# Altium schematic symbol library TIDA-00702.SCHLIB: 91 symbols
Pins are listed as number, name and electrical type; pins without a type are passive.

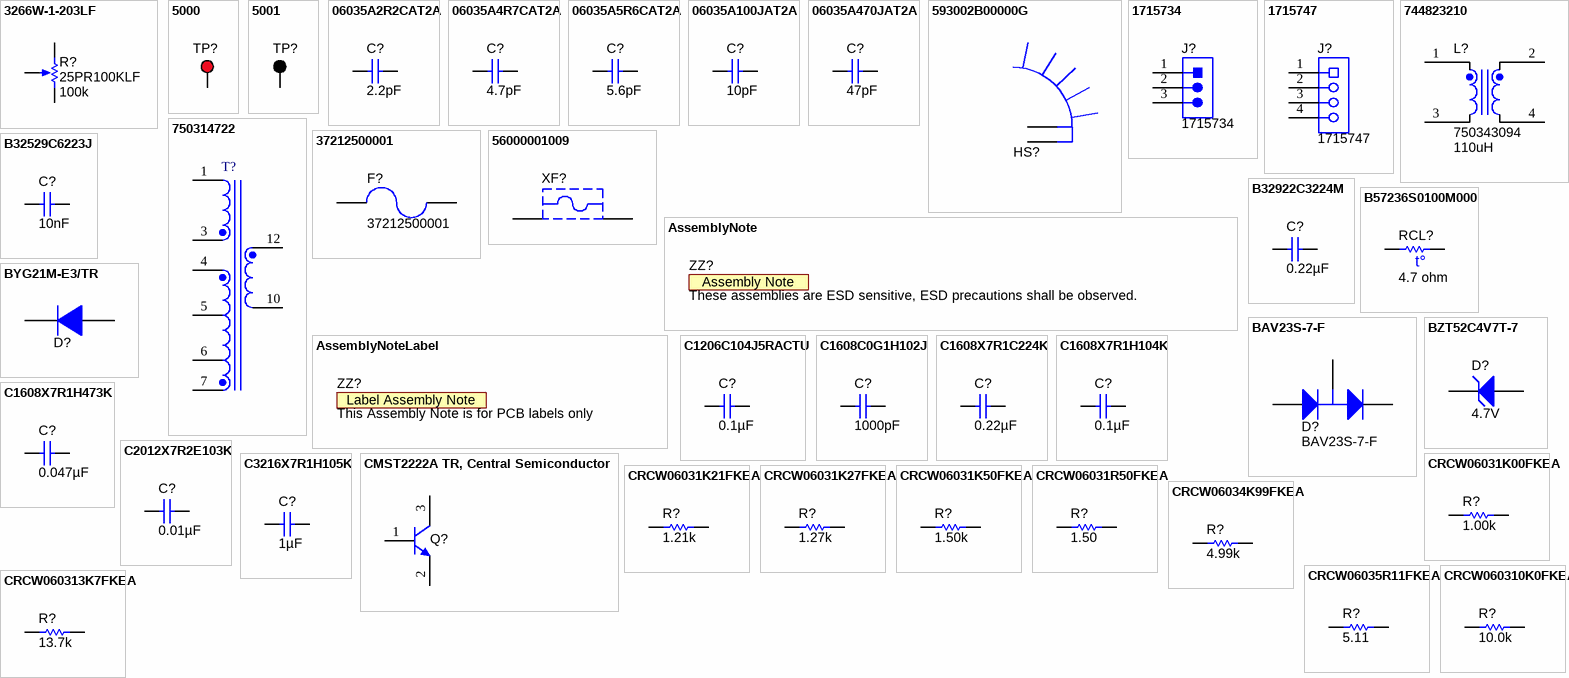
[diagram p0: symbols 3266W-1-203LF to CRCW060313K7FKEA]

## 3266W-1-203LF
designator R?, comment 25PR100KLF  value 100k
TRIMMER 100K OHM 0.5W TH; Manufacturer: TT Electronics/BI; Sim Note: Enter the Resistance value and the set point into parameter fields.
simulation model POT (Potentiometer)
footprint TRIM_3266W
footprint POT_25PXXXXXX (Potentiometer, 25p series, through hole, 3 pin)
pins: 1 CCW, 2 WIPER, 3 CW
1 alternate drawing of the same symbol

## 5000
designator TP?  (value not drawn)
Test Point, Miniature, Red, TH; Manufacturer: Keystone; CompType: Test Point Loop; U/M: EA
footprint Keystone5000
pins: 1

## 5001
designator TP?  (value not drawn)
Test Point, Miniature, Black, TH; Manufacturer: Keystone; CompType: Test Point Loop; U/M: EA
footprint Keystone5001 (For Keystone 500x miniature loop terminals)
pins: 1

## 06035A2R2CAT2A
designator C?  ValueDisplayed: 2.2pF  (hidden comment: 06035A2R2CAT2A)
CAP, CERM, 2.2 pF, 50 V, +/- 11%, C0G/NP0, 0603; Manufacturer: AVX; Polarized: N; CompType: Capacitor; Value: 2.2pF; U/M: EA; Cap_F: 0.0000000000022; Tolerance_%: 11; ESR_ohm: 1.033; Value1: 1.033 ohm; VDC_V: 50; Value2: 50V; TaMin_C: -55; TaMax_C: 125; Cap_Case: 0603
signal-integrity model Cap
simulation model Cap
footprint 0603
footprint 0603M
footprint 0603L
footprint 0603_HV
footprint 0603S
pins: 1, 2

## 06035A4R7CAT2A
designator C?  ValueDisplayed: 4.7pF  (hidden comment: 06035A4R7CAT2A)
CAP, CERM, 4.7 pF, 50 V, +/- 5%, C0G/NP0, 0603; Manufacturer: AVX; Polarized: N; CompType: Capacitor; Value: 4.7pF; U/M: EA; Cap_F: 0.0000000000047; Tolerance_%: 5; ESR_ohm: 0.633; Value1: 0.633 ohm; VDC_V: 50; Value2: 50V; TaMin_C: -55; TaMax_C: 125; Cap_Case: 0603
signal-integrity model Cap
simulation model Cap
footprint 0603
footprint 0603M
footprint 0603L
footprint 0603_HV
footprint 0603S
pins: 1, 2

## 06035A5R6CAT2A
designator C?  ValueDisplayed: 5.6pF  (hidden comment: 06035A5R6CAT2A)
CAP, CERM, 5.6 pF, 50 V, +/- 5%, C0G/NP0, 0603; Manufacturer: AVX; Polarized: N; CompType: Capacitor; Value: 5.6pF; U/M: EA; Cap_F: 0.0000000000056; Tolerance_%: 5; ESR_ohm: 0.568; Value1: 0.568 ohm; VDC_V: 50; Value2: 50V; TaMin_C: -55; TaMax_C: 125; Cap_Case: 0603
signal-integrity model Cap
simulation model Cap
footprint 0603
footprint 0603M
footprint 0603L
footprint 0603_HV
footprint 0603S
pins: 1, 2

## 06035A100JAT2A
designator C?  ValueDisplayed: 10pF  (hidden comment: 06035A100JAT2A)
CAP, CERM, 10 pF, 50 V, +/- 5%, C0G/NP0, 0603; Manufacturer: AVX; Polarized: N; CompType: Capacitor; Value: 10pF; U/M: EA; Cap_F: 0.00000000001; Tolerance_%: 5; ESR_ohm: 0.403; Value1: 0.403 ohm; VDC_V: 50; Value2: 50V; TaMin_C: -55; TaMax_C: 125; Cap_Case: 0603
signal-integrity model Cap
simulation model Cap
footprint 0603
footprint 0603M
footprint 0603L
footprint 0603_HV
footprint 0603S
pins: 1, 2

## 06035A470JAT2A
designator C?  ValueDisplayed: 47pF  (hidden comment: 06035A470JAT2A)
CAP, CERM, 47 pF, 50 V, +/- 5%, C0G/NP0, 0603; Manufacturer: AVX; Polarized: N; CompType: Capacitor; Value: 47pF; U/M: EA; Cap_F: 0.000000000047; Tolerance_%: 5; ESR_ohm: 0.174; Value1: 0.174 ohm; VDC_V: 50; Value2: 50V; TaMin_C: -55; TaMax_C: 125; Cap_Case: 0603
signal-integrity model Cap
simulation model Cap
footprint 0603
footprint 0603M
footprint 0603L
footprint 0603_HV
footprint 0603S
pins: 1, 2

## 593002B00000G
designator HS?  (value not drawn)
HEATSINK TWISTED FIN TO-220 Vertical; Manufacturer: Aavid Thermalloy; SymbolCreator: a0799628; Value: 13.4°C/W
footprint HSINK_593002B00000G (Heat Sink, TO-220 Vertical)
footprint HEATSINK_593002B03400G (HEATSINK, 25X12.7X29.97 MM)
pins: 1, 2

## 1715734
designator J?
TERM BLOCK 3POS 5.08MM, TH; Manufacturer: Phoenix Contact; SymbolCreator: a0799628; CompType: Header; U/M: EA
footprint Phoenix_1715734 (Phoenix)
pins: 1, 2, 3
3 alternate drawings of the same symbol

## 1715747
designator J?
Terminal Block, 5.08mm, 4x1, TH; Manufacturer: Phoenix Contact; SymbolCreator: a0411947; U/M: EA
footprint Phoenix_1715747 (Terminal Block, 5.08mm, 4x1, TH)
pins: 1, 2, 3, 4

## 744823210
designator L?, comment 750343094  ValueDisplayed: 110uH
Coupled inductor, 7mH, 2 A, 0.045 ohm, 3.7-7.1 mH; Manufacturer: Wurth Elektronik; SymbolCreator: a0412235; Value: 100uH; DCR_ohm: 0.045; Isat: 2; Tolerance_%: 30
footprint IND_750343094 (INDUCTOR, TH-4P)
pins: 1, 2, 3, 4

## 750314722
designator T?
Transformer, 230uH, SMT; Manufacturer: Wurth Elektronik; SymbolCreator: x0208326; DCR_Ohm: 6.05; Value: 8mH; U/M: EA
footprint Trans_FBtrans00702 (DC-DC CONVERTER 12-Pin Transformer, THT, Vertical)
pins: 1, 3, 4, 5, 6, 7, 10, 12

## 37212500001
designator F?
Fuse, 2.5 A, 250 V, TH; Manufacturer: Littelfuse; U/M: EA; OpeningTime_200%_max: 2; VDC_V: 250; Irating_A: 2.5; Vdrop: 0.08; Soldering_Wave_MaxTemp_C: 260; Soldering_Wave_MaxTime_s: 5
footprint FUSE_372
pins: 1, 2

## 56000001009
designator XF?  (value not drawn)
FUSE HOLDER RADIAL 250V 6.3A PCB; Manufacturer: Littelfuse; SymbolCreator: a0412235; Value: TR5
footprint FuseHolder_560000010 (Littelfuse fuse holder TR5)
pins: 1, 2

## AssemblyNote
designator ZZ?, comment These assemblies are ESD sensitive, ESD precautions shall be observed.  (no BOM)
SymbolCreator: codlsc; CompType: AssemblyNote
footprint AssemblyNote

## AssemblyNoteLabel
designator ZZ?, comment This Assembly Note is for PCB labels only  (no BOM)
SymbolCreator: a0412235
footprint AssemblyNoteLabel

## B32529C6223J
designator C?, comment ValueDisplayed: 10nF  (hidden comment: B32529C8103K)
CAP FILM 10000PF 10% 630VDC RAD; Manufacturer: EPCOS (TDK); Polarized: N; CompType: Capacitor; Value: 10nF; U/M: EA; Tolerance_%: 5; Value1: Unknown; VDC_V: 630; Value2: 630V; TaMin_C: -55; TaMax_C: 125
signal-integrity model Cap
simulation model Cap
footprint B32529_450x950x730
pins: 1, 2

## B32922C3224M
designator C?  ValueDisplayed: 0.22µF  (hidden comment: B32922C3224M)
CAP, Film, 0.22 µF, 630 V, +/- 20%, TH; Manufacturer: TDK; Polarized: N; CompType: Capacitor; Value: 0.22uF; U/M: EA; Cap_F: 0.00000022; Tolerance_%: 20; Value1: Unknown; VDC_V: 630; Value2: 630V; TaMax_C: 110
signal-integrity model Cap
simulation model Cap
footprint B32922_12.5mm (Epcos film capacitors, 15mm spacing)
pins: 1, 2

## B57236S0100M000
designator RCL?, comment value 4.7 ohm  (hidden comment: B57236S479M)
ICL 4.7 OHM 20% 4.6A 11.51MM; Manufacturer: EPCOS (TDK); CompType: ThermistorNTC; Tolerance_%: 20; Power_W: 2.1; U/M: EA; TaMin_C: -55; TaMax_C: 170
footprint THERM_B57236S0 (EPCOS)
pins: 1, 2

## BAV23S-7-F
designator D?
Diode, Switching, 200 V, 0.4 A, SOT-23; Manufacturer: Diodes Inc.; U/M: EA; Vf_V: 1.25; Value: 200V; Value1: 0.4A; Value2: 1.25V; Io_A: 0.4; Vr_V: 200; TJmax_C: 150; RJC_CperW: 357
footprint SOT-23 (SOT23, 3-Leads, Body 2.9x1.3mm, Pitch 0.95mm, Lead Span 2.5mm, IPC Medium Density)
footprint SOT-23M
footprint SOT-23L
pins: 1 A, 2 K, 3 C
1 alternate drawing of the same symbol

## BYG21M-E3/TR
designator D?  (value not drawn)
Diode, Fast Rectifier, 1000 V, 1.5 A, SMA; Manufacturer: Vishay-Semiconductor; U/M: EA; Vf_V: 1.6; Value: 1000V; Value1: 1.5A; Value2: 1.6V; Io_A: 1.5; Vr_V: 1000; TJmax_C: 150
signal-integrity model Diode
footprint SMA
pins: 1 K, 2 A

## BZT52C4V7T-7
designator D?  value 4.7V  (hidden comment: BZT52C4V7T-7)
Diode, Zener, 4.7 V, 300 mW, SOD-523; Manufacturer: Diodes Inc.; U/M: EA; SymbolCreator: a0412235; Power_W: 0.3; Vz_V: 4.7; Value1: 0.3W; RJA_CperW: 417
signal-integrity model Diode
footprint SOD-523
pins: 1 K, 2 A

## C1206C104J5RACTU
designator C?  ValueDisplayed: 0.1µF  (hidden comment: C1206C104J5RACTU)
CAP, CERM, 0.1 µF, 50 V, +/- 5%, X7R, 1206; Manufacturer: Kemet; Polarized: N; CompType: Capacitor; Value: 0.1uF; U/M: EA; Cap_F: 0.0000001; Tolerance_%: 5; ESR_ohm: 0.059; Value1: 0.059 ohm; VDC_V: 50; Value2: 50V; IRMS_A: 1.2; TaMin_C: -55; TaMax_C: 125; Cap_Case: 1206
signal-integrity model Cap
simulation model Cap
footprint 1206
footprint 1206M
footprint 1206L
pins: 1, 2

## C1608C0G1H102J
designator C?  ValueDisplayed: 1000pF  (hidden comment: C1608C0G1H102J)
CAP, CERM, 1000 pF, 50 V, +/- 5%, C0G/NP0, 0603; Manufacturer: TDK; Polarized: N; CompType: Capacitor; Value: 1000pF; U/M: EA; Cap_F: 0.000000001; Tolerance_%: 5; ESR_ohm: 0.0563; Value1: 0.0563 ohm; VDC_V: 50; Value2: 50V; TaMin_C: -55; TaMax_C: 125; Cap_Case: 0603
signal-integrity model Cap
simulation model Cap
footprint 0603
footprint 0603M
footprint 0603L
footprint 0603_HV
footprint 0603S
pins: 1, 2

## C1608X7R1C224K
designator C?  ValueDisplayed: 0.22µF  (hidden comment: C1608X7R1C224K)
CAP, CERM, 0.22 µF, 16 V, +/- 10%, X7R, 0603; Manufacturer: TDK; Polarized: N; CompType: Capacitor; Value: 0.22uF; U/M: EA; Cap_F: 0.00000022; Tolerance_%: 10; ESR_ohm: 0.0125; Value1: 0.0125 ohm; VDC_V: 16; Value2: 16V; TaMin_C: -55; TaMax_C: 125; Cap_Case: 0603
signal-integrity model Cap
simulation model Cap
footprint 0603
footprint 0603M
footprint 0603L
footprint 0603_HV
footprint 0603S
pins: 1, 2

## C1608X7R1H104K
designator C?  ValueDisplayed: 0.1µF  (hidden comment: C1608X7R1H104K)
CAP, CERM, 0.1 µF, 50 V, +/- 10%, X7R, 0603; Manufacturer: TDK; Polarized: N; CompType: Capacitor; Value: 0.1uF; U/M: EA; Cap_F: 0.0000001; Tolerance_%: 10; ESR_ohm: 0.017; Value1: 0.017 ohm; VDC_V: 50; Value2: 50V; TaMin_C: -55; TaMax_C: 125; Cap_Case: 0603
signal-integrity model Cap
simulation model Cap
footprint 0603
footprint 0603M
footprint 0603L
footprint 0603_HV
footprint 0603S
pins: 1, 2

## C1608X7R1H473K
designator C?  ValueDisplayed: 0.047µF  (hidden comment: C1608X7R1H473K)
CAP, CERM, 0.047 µF, 50 V, +/- 10%, X7R, 0603; Manufacturer: TDK; Polarized: N; CompType: Capacitor; Value: 0.047uF; U/M: EA; Cap_F: 0.000000047; Tolerance_%: 10; ESR_ohm: 0.0234; Value1: 0.0234 ohm; VDC_V: 50; Value2: 50V; TaMin_C: -55; TaMax_C: 125; Cap_Case: 0603
signal-integrity model Cap
simulation model Cap
footprint 0603
footprint 0603M
footprint 0603L
footprint 0603_HV
footprint 0603S
pins: 1, 2

## C2012X7R2E103K
designator C?  ValueDisplayed: 0.01µF  (hidden comment: C2012X7R2E103K)
CAP, CERM, 0.01 µF, 250 V, +/- 10%, X7R, 0805; Manufacturer: TDK; Polarized: N; CompType: Capacitor; Value: 0.01uF; U/M: EA; Cap_F: 0.00000001; Tolerance_%: 10; ESR_ohm: 0.0681; Value1: 0.0681 ohm; VDC_V: 250; Value2: 250V; TaMin_C: -55; TaMax_C: 125; Cap_Case: 0805
signal-integrity model Cap
simulation model Cap
footprint 0805_HV
footprint 0805
footprint 0805M
footprint 0805L
pins: 1, 2

## C3216X7R1H105K
designator C?  ValueDisplayed: 1µF  (hidden comment: C3216X7R1H105K)
CAP, CERM, 1 µF, 50 V, +/- 10%, X7R, 1206; Manufacturer: TDK; Polarized: N; CompType: Capacitor; Value: 1uF; U/M: EA; Cap_F: 0.000001; Tolerance_%: 10; ESR_ohm: 0.01; Value1: 0.01 ohm; VDC_V: 50; Value2: 50V; IRMS_A: 3.2; TaMin_C: -55; TaMax_C: 125; Cap_Case: 1206
signal-integrity model Cap
simulation model Cap
footprint 1206
footprint 1206M
footprint 1206L
pins: 1, 2

## CMST2222A TR, Central Semiconductor
designator Q?, comment MMBT4401WT1G  (value not drawn)
Transistor, NPN, 40 V, 0.6 A, SOT-323; Manufacturer: ON Semiconductor; CompType: BJT; PNP: 0; NPN: 1; Vceo_V: 40; Vcesat1_V: 0.3; Value: 40 V; IcRated_A: 0.6; Value1: 0.6 A; TaMin_C: -65; TaMax_C: 150; U/M: EA
footprint SOT-323 (Zetex recommended land pattern.  March 2007)
pins: 1 B, 2 E, 3 C

## CRCW06031K00FKEA
designator R?  ValueDisplayed: 1.00k  (hidden comment: CRCW06031K00FKEA)
RES, 1.00 k, 1%, 0.1 W, 0603; Manufacturer: Vishay-Dale; CompType: Resistor; Value: 1.00k; Res_ohm: 1000; Value_Code: 1k00; Tolerance_%: 1; Power_W: 0.1; Value2: 0.1W; VDC_V: 75; TempCo: 100 ppm/C; EIA_Code: E96; U/M: EA
signal-integrity model Resistor
simulation model Resistor
footprint 0603
footprint 0603M
footprint 0603L
footprint 0603_HV
footprint 0603S
pins: 1, 2

## CRCW06031K21FKEA
designator R?  ValueDisplayed: 1.21k  (hidden comment: CRCW06031K21FKEA)
RES, 1.21 k, 1%, 0.1 W, 0603; Manufacturer: Vishay-Dale; CompType: Resistor; Value: 1.21k; Res_ohm: 1210; Value_Code: 1k21; Tolerance_%: 1; Power_W: 0.1; Value2: 0.1W; VDC_V: 75; TempCo: 100 ppm/C; EIA_Code: E96; U/M: EA; AEC Category: Q200
signal-integrity model Resistor
simulation model Resistor
footprint 0603
footprint 0603M
footprint 0603L
footprint 0603_HV
footprint 0603S
pins: 1, 2

## CRCW06031K27FKEA
designator R?  ValueDisplayed: 1.27k  (hidden comment: CRCW06031K27FKEA)
RES, 1.27 k, 1%, 0.1 W, 0603; Manufacturer: Vishay-Dale; CompType: Resistor; Value: 1.27k; Res_ohm: 1270; Value_Code: 1k27; Tolerance_%: 1; Power_W: 0.1; Value2: 0.1W; VDC_V: 75; TempCo: 100 ppm/C; EIA_Code: E96; U/M: EA
signal-integrity model Resistor
simulation model Resistor
footprint 0603
footprint 0603M
footprint 0603L
footprint 0603_HV
footprint 0603S
pins: 1, 2

## CRCW06031K50FKEA
designator R?  ValueDisplayed: 1.50k  (hidden comment: CRCW06031K50FKEA)
RES, 1.50 k, 1%, 0.1 W, 0603; Manufacturer: Vishay-Dale; CompType: Resistor; Value: 1.50k; Res_ohm: 1500; Value_Code: 1k50; Tolerance_%: 1; Power_W: 0.1; Value2: 0.1W; VDC_V: 75; TempCo: 100 ppm/C; EIA_Code: E96; U/M: EA
signal-integrity model Resistor
simulation model Resistor
footprint 0603
footprint 0603M
footprint 0603L
footprint 0603_HV
footprint 0603S
pins: 1, 2

## CRCW06031R50FKEA
designator R?  ValueDisplayed: 1.50  (hidden comment: CRCW06031R50FKEA)
RES, 1.50, 1%, 0.1 W, 0603; Manufacturer: Vishay-Dale; CompType: Resistor; Value: 1.50; Res_ohm: 1.5; Value_Code: 1R50; Tolerance_%: 1; Power_W: 0.1; Value2: 0.1W; VDC_V: 75; TempCo: 100 ppm/C; EIA_Code: E96; U/M: EA
signal-integrity model Resistor
simulation model Resistor
footprint 0603
footprint 0603M
footprint 0603L
footprint 0603_HV
footprint 0603S
pins: 1, 2

## CRCW06034K99FKEA
designator R?  ValueDisplayed: 4.99k  (hidden comment: CRCW06034K99FKEA)
RES, 4.99 k, 1%, 0.1 W, 0603; Manufacturer: Vishay-Dale; CompType: Resistor; Value: 4.99k; Res_ohm: 4990; Value_Code: 4k99; Tolerance_%: 1; Power_W: 0.1; Value2: 0.1W; VDC_V: 75; TempCo: 100 ppm/C; EIA_Code: E96; U/M: EA
signal-integrity model Resistor
simulation model Resistor
footprint 0603
footprint 0603M
footprint 0603L
footprint 0603_HV
footprint 0603S
pins: 1, 2

## CRCW06035R11FKEA
designator R?  ValueDisplayed: 5.11  (hidden comment: CRCW06035R11FKEA)
RES, 5.11, 1%, 0.1 W, 0603; Manufacturer: Vishay-Dale; CompType: Resistor; Value: 5.11; Value_Code: 5R11; Tolerance_%: 1; Power_W: 0.1; Value2: 0.1W; VDC_V: 75; TempCo: 100 ppm/C; EIA_Code: E96; U/M: EA; AEC Category: Q200
signal-integrity model Resistor
simulation model Resistor
footprint 0603
footprint 0603M
footprint 0603L
footprint 0603_HV
footprint 0603S
pins: 1, 2

## CRCW060310K0FKEA
designator R?  ValueDisplayed: 10.0k  (hidden comment: CRCW060310K0FKEA)
RES, 10.0 k, 1%, 0.1 W, 0603; Manufacturer: Vishay-Dale; CompType: Resistor; Value: 10.0k; Res_ohm: 10000; Value_Code: 10k0; Tolerance_%: 1; Power_W: 0.1; Value2: 0.1W; VDC_V: 75; TempCo: 100 ppm/C; EIA_Code: E96; U/M: EA
signal-integrity model Resistor
simulation model Resistor
footprint 0603
footprint 0603M
footprint 0603L
footprint 0603_HV
footprint 0603S
pins: 1, 2

## CRCW060313K7FKEA
designator R?  ValueDisplayed: 13.7k  (hidden comment: CRCW060313K7FKEA)
RES, 13.7 k, 1%, 0.1 W, 0603; Manufacturer: Vishay-Dale; CompType: Resistor; Value: 13.7k; Res_ohm: 13700; Value_Code: 13k7; Tolerance_%: 1; Power_W: 0.1; Value2: 0.1W; VDC_V: 75; TempCo: 100 ppm/C; EIA_Code: E96; U/M: EA
signal-integrity model Resistor
simulation model Resistor
footprint 0603
footprint 0603M
footprint 0603L
footprint 0603_HV
footprint 0603S
pins: 1, 2

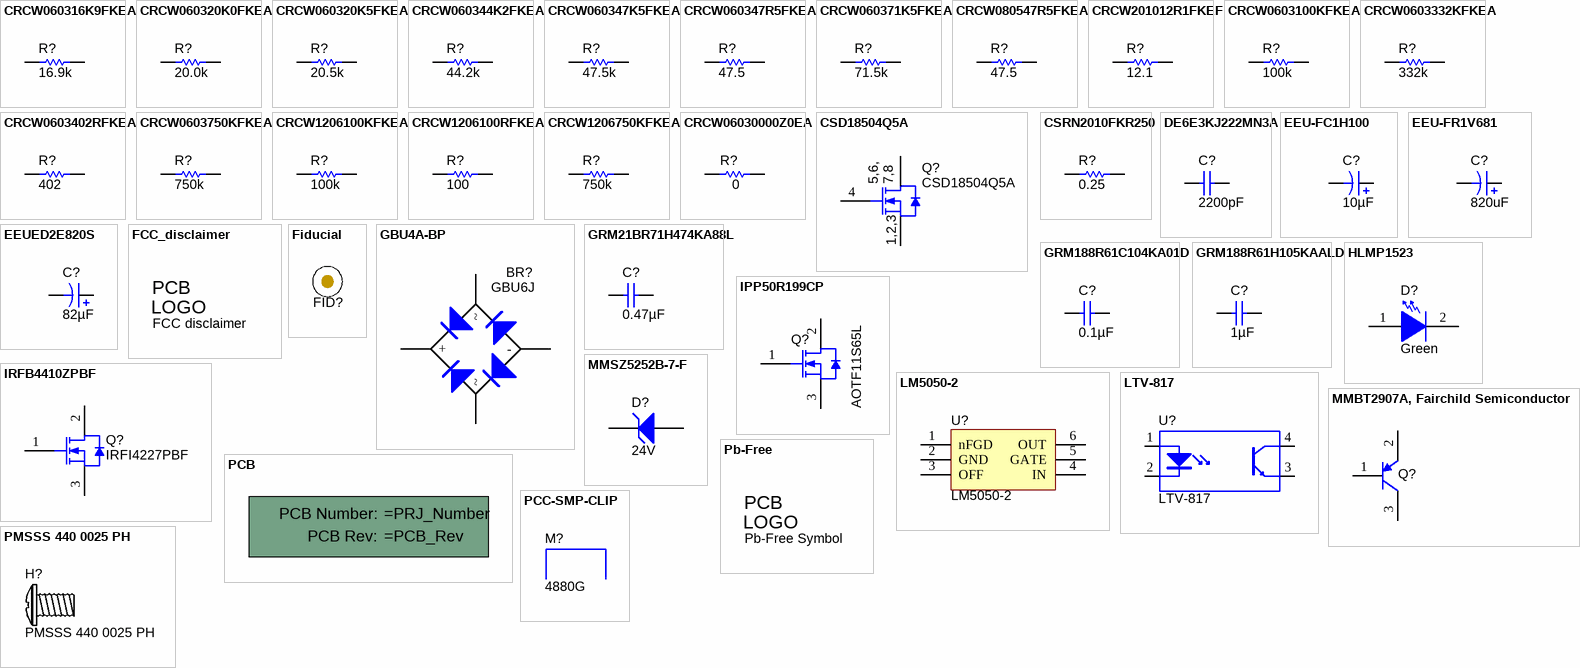
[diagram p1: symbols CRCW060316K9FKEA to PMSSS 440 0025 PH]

## CRCW060316K9FKEA
designator R?  ValueDisplayed: 16.9k  (hidden comment: CRCW060316K9FKEA)
RES, 16.9 k, 1%, 0.1 W, 0603; Manufacturer: Vishay-Dale; CompType: Resistor; Value: 16.9k; Res_ohm: 16900; Value_Code: 16k9; Tolerance_%: 1; Power_W: 0.1; Value2: 0.1W; VDC_V: 75; TempCo: 100 ppm/C; EIA_Code: E96; U/M: EA
signal-integrity model Resistor
simulation model Resistor
footprint 0603
footprint 0603M
footprint 0603L
footprint 0603_HV
footprint 0603S
pins: 1, 2

## CRCW060320K0FKEA
designator R?  ValueDisplayed: 20.0k  (hidden comment: CRCW060320K0FKEA)
RES, 20.0 k, 1%, 0.1 W, 0603; Manufacturer: Vishay-Dale; CompType: Resistor; Value: 20.0k; Res_ohm: 20000; Value_Code: 20k0; Tolerance_%: 1; Power_W: 0.1; Value2: 0.1W; VDC_V: 75; TempCo: 100 ppm/C; EIA_Code: E96; U/M: EA
signal-integrity model Resistor
simulation model Resistor
footprint 0603
footprint 0603M
footprint 0603L
footprint 0603_HV
footprint 0603S
pins: 1, 2

## CRCW060320K5FKEA
designator R?  ValueDisplayed: 20.5k  (hidden comment: CRCW060320K5FKEA)
RES, 20.5 k, 1%, 0.1 W, 0603; Manufacturer: Vishay-Dale; CompType: Resistor; Value: 20.5k; Res_ohm: 20500; Value_Code: 20k5; Tolerance_%: 1; Power_W: 0.1; Value2: 0.1W; VDC_V: 75; TempCo: 100 ppm/C; EIA_Code: E96; U/M: EA
signal-integrity model Resistor
simulation model Resistor
footprint 0603
footprint 0603M
footprint 0603L
footprint 0603_HV
footprint 0603S
pins: 1, 2

## CRCW060344K2FKEA
designator R?  ValueDisplayed: 44.2k  (hidden comment: CRCW060344K2FKEA)
RES, 44.2 k, 1%, 0.1 W, 0603; Manufacturer: Vishay-Dale; CompType: Resistor; Value: 44.2k; Res_ohm: 44200; Value_Code: 44k2; Tolerance_%: 1; Power_W: 0.1; Value2: 0.1W; VDC_V: 75; TempCo: 100 ppm/C; EIA_Code: E96; U/M: EA
signal-integrity model Resistor
simulation model Resistor
footprint 0603
footprint 0603M
footprint 0603L
footprint 0603_HV
footprint 0603S
pins: 1, 2

## CRCW060347K5FKEA
designator R?  ValueDisplayed: 47.5k  (hidden comment: CRCW060347K5FKEA)
RES, 47.5 k, 1%, 0.1 W, 0603; Manufacturer: Vishay-Dale; CompType: Resistor; Value: 47.5k; Res_ohm: 47500; Value_Code: 47k5; Tolerance_%: 1; Power_W: 0.1; Value2: 0.1W; VDC_V: 75; TempCo: 100 ppm/C; EIA_Code: E96; U/M: EA
signal-integrity model Resistor
simulation model Resistor
footprint 0603
footprint 0603M
footprint 0603L
footprint 0603_HV
footprint 0603S
pins: 1, 2

## CRCW060347R5FKEA
designator R?  ValueDisplayed: 47.5  (hidden comment: CRCW060347R5FKEA)
RES, 47.5, 1%, 0.1 W, 0603; Manufacturer: Vishay-Dale; CompType: Resistor; Value: 47.5; Value_Code: 47R5; Tolerance_%: 1; Power_W: 0.1; Value2: 0.1W; VDC_V: 75; TempCo: 100 ppm/C; EIA_Code: E96; U/M: EA
signal-integrity model Resistor
simulation model Resistor
footprint 0603
footprint 0603M
footprint 0603L
footprint 0603_HV
footprint 0603S
pins: 1, 2

## CRCW060371K5FKEA
designator R?  ValueDisplayed: 71.5k  (hidden comment: CRCW060371K5FKEA)
RES, 71.5 k, 1%, 0.1 W, 0603; Manufacturer: Vishay-Dale; CompType: Resistor; Value: 71.5k; Res_ohm: 71500; Value_Code: 71k5; Tolerance_%: 1; Power_W: 0.1; Value2: 0.1W; VDC_V: 75; TempCo: 100 ppm/C; EIA_Code: E96; U/M: EA
signal-integrity model Resistor
simulation model Resistor
footprint 0603
footprint 0603M
footprint 0603L
footprint 0603_HV
footprint 0603S
pins: 1, 2

## CRCW080547R5FKEA
designator R?  ValueDisplayed: 47.5  (hidden comment: CRCW080547R5FKEA)
RES, 47.5, 1%, 0.125 W, 0805; Manufacturer: Vishay-Dale; CompType: Resistor; Value: 47.5; Value_Code: 47R5; Tolerance_%: 1; Power_W: 0.125; Value2: 0.125W; VDC_V: 150; TempCo: 100 ppm/C; EIA_Code: E96; U/M: EA
signal-integrity model Resistor
simulation model Resistor
footprint 0805_HV
footprint 0805
footprint 0805M
footprint 0805L
pins: 1, 2

## CRCW201012R1FKEF
designator R?  ValueDisplayed: 12.1  (hidden comment: CRCW201012R1FKEF)
RES, 12.1, 1%, 0.75 W, 2010; Manufacturer: Vishay-Dale; CompType: Resistor; Value: 12.1; Value_Code: 12R1; Tolerance_%: 1; Power_W: 0.75; Value2: 0.75W; VDC_V: 400; TempCo: 100 ppm/C; EIA_Code: E96; U/M: EA
signal-integrity model Resistor
simulation model Resistor
footprint 2010
footprint 2010M
footprint 2010L
pins: 1, 2

## CRCW0603100KFKEA
designator R?  ValueDisplayed: 100k  (hidden comment: CRCW0603100KFKEA)
RES, 100 k, 1%, 0.1 W, 0603; Manufacturer: Vishay-Dale; CompType: Resistor; Value: 100k; Res_ohm: 100000; Tolerance_%: 1; Power_W: 0.1; Value2: 0.1W; VDC_V: 75; TempCo: 100 ppm/C; EIA_Code: E96; U/M: EA
signal-integrity model Resistor
simulation model Resistor
footprint 0603
footprint 0603M
footprint 0603L
footprint 0603_HV
footprint 0603S
pins: 1, 2

## CRCW0603332KFKEA
designator R?  ValueDisplayed: 332k  (hidden comment: CRCW0603332KFKEA)
RES, 332 k, 1%, 0.1 W, 0603; Manufacturer: Vishay-Dale; CompType: Resistor; Value: 332k; Res_ohm: 332000; Tolerance_%: 1; Power_W: 0.1; Value2: 0.1W; VDC_V: 75; TempCo: 100 ppm/C; EIA_Code: E96; U/M: EA
signal-integrity model Resistor
simulation model Resistor
footprint 0603
footprint 0603M
footprint 0603L
footprint 0603_HV
footprint 0603S
pins: 1, 2

## CRCW0603402RFKEA
designator R?  ValueDisplayed: 402  (hidden comment: CRCW0603402RFKEA)
RES, 402, 1%, 0.1 W, 0603; Manufacturer: Vishay-Dale; CompType: Resistor; Value: 402; Value_Code: 402R; Tolerance_%: 1; Power_W: 0.1; Value2: 0.1W; VDC_V: 75; TempCo: 100 ppm/C; EIA_Code: E96; U/M: EA
signal-integrity model Resistor
simulation model Resistor
footprint 0603
footprint 0603M
footprint 0603L
footprint 0603_HV
footprint 0603S
pins: 1, 2

## CRCW0603750KFKEA
designator R?  ValueDisplayed: 750k  (hidden comment: CRCW0603750KFKEA)
RES, 750 k, 1%, 0.1 W, 0603; Manufacturer: Vishay-Dale; CompType: Resistor; Value: 750k; Res_ohm: 750000; Tolerance_%: 1; Power_W: 0.1; Value2: 0.1W; VDC_V: 75; TempCo: 100 ppm/C; EIA_Code: E96; U/M: EA
signal-integrity model Resistor
simulation model Resistor
footprint 0603
footprint 0603M
footprint 0603L
footprint 0603_HV
footprint 0603S
pins: 1, 2

## CRCW1206100KFKEA
designator R?  ValueDisplayed: 100k  (hidden comment: CRCW1206100KFKEA)
RES, 100 k, 1%, 0.25 W, 1206; Manufacturer: Vishay-Dale; CompType: Resistor; Value: 100k; Res_ohm: 100000; Tolerance_%: 1; Power_W: 0.25; Value2: 0.25W; VDC_V: 200; TempCo: 100 ppm/C; EIA_Code: E96; U/M: EA
signal-integrity model Resistor
simulation model Resistor
footprint 1206
footprint 1206M
footprint 1206L
pins: 1, 2

## CRCW1206100RFKEA
designator R?  ValueDisplayed: 100  (hidden comment: CRCW1206100RFKEA)
RES, 100, 1%, 0.25 W, 1206; Manufacturer: Vishay-Dale; CompType: Resistor; Value: 100; Value_Code: 100R; Tolerance_%: 1; Power_W: 0.25; Value2: 0.25W; VDC_V: 200; TempCo: 100 ppm/C; EIA_Code: E96; U/M: EA
signal-integrity model Resistor
simulation model Resistor
footprint 1206
footprint 1206M
footprint 1206L
pins: 1, 2

## CRCW1206750KFKEA
designator R?  ValueDisplayed: 750k  (hidden comment: CRCW1206750KFKEA)
RES, 750 k, 1%, 0.25 W, 1206; Manufacturer: Vishay-Dale; Value: 750k; CompType: Resistor; Res_ohm: 750000; Tolerance_%: 1; Power_W: 0.25; Value2: 0.25W; VDC_V: 200; TempCo: 100 ppm/C; EIA_Code: E96; U/M: EA
signal-integrity model Resistor
simulation model Resistor
footprint 1206
footprint 1206M
footprint 1206L
pins: 1, 2

## CRCW06030000Z0EA
designator R?  ValueDisplayed: 0  (hidden comment: CRCW06030000Z0EA)
RES, 0, 5%, 0.1 W, 0603; Manufacturer: Vishay-Dale; CompType: Resistor; Value: 0; Value_Code: 0000; Tolerance_%: 5; Power_W: 0.1; Value2: 0.1W; VDC_V: 75; TempCo: 200 ppm/C; EIA_Code: E24; U/M: EA; AEC Category: Q200
signal-integrity model Resistor
simulation model Resistor
footprint 0603 (0603 from SM-752 data)
footprint 0603M
footprint 0603L
footprint 0603_HV
footprint 0603S
pins: 1, 2

## CSD18504Q5A
designator Q?
MOSFET, N-CH, 40 V, 15 A, SON 5x6mm; Manufacturer: Texas Instruments; Alternate Manufacturer: None; U/M: EA; ChType: N; Value: 40V; VdsMax_V: 40; Value1: 0.0098 ohm; Rdson45_ohm: 0.0098; Value2: 7.7 nC; QgTyp_nC: 7.7; Vgs_V: 20; IdsMax_A: 15
footprint TRANS_NexFET_Q5A
pins: 1 S, 2 S, 3 S, 4 G, 5 D, 6 D, 7 D, 8 D, 9 D

## CSRN2010FKR250
designator R?  ValueDisplayed: 0.25  (hidden comment: CSRN2010FKR250)
RES, 0.25, 1%, 1 W, 2010; Manufacturer: Stackpole Electronics Inc; CompType: Resistor; Value: 0.25; Value_Code: R250; Tolerance_%: 1; Value2: 1W; TempCo: 250 ppm/C; U/M: EA
signal-integrity model Resistor
simulation model Resistor
footprint 2010
footprint 2010M
footprint 2010L
pins: 1, 2

## DE6E3KJ222MN3A
designator C?, comment ValueDisplayed: 2200pF  (hidden comment: CS80ZU2GA222MYNKA)
CAP CER 2200PF 300VAC 20% RADIAL; Manufacturer: TDK Corporation; Polarized: N; CompType: Capacitor; Value: 2.2nF; U/M: EA; Cap_F: 0.0000000022; Tolerance_%: 20; Value1: Unknown; VDC_V: 300; Value2: 300V; TempCo: E; TaMin_C: -40; TaMax_C: 125
signal-integrity model Cap
simulation model Cap
footprint E_900x700x900
pins: 1, 2

## EEU-FC1H100
designator C?, comment ValueDisplayed: 10µF  (hidden comment: UVR1H100MDD6TP)
CAP ALUM 10UF 20% 50V RADIAL; Manufacturer: Nichicon; Polarized: Y; CompType: Capacitor; U/M: EA; Cap_F: 0.00001; Tolerance_%: 20; Value1: 2.5 ohm; VDC_V: 50; ESR_ohm: 2.5; IRMS_A: 0.09; TaMin_C: -55; TaMax_C: 105; Cap_Case: 4.0x11.0
signal-integrity model Cap
simulation model Cap
footprint FC_400x1100
pins: 1 +, 2 -

## EEU-FR1V681
designator C?, comment ValueDisplayed: 820uF  (hidden comment: EEU-FR1V821L)
CAP ALUM 820UF 20% 35V RADIAL; Manufacturer: Panasonic; Polarized: Y; CompType: Capacitor; U/M: EA; Cap_F: 0.00082; Tolerance_%: 20; Value1: Unknown; VDC_V: 35; IRMS_A: 2.47; TaMin_C: -40; TaMax_C: 105; Cap_Case: 10x27
signal-integrity model Cap
simulation model Cap
footprint CAPPR5-10X20
footprint CAPPR5-10x20_HorizontalUp
pins: 1 +, 2 -

## EEUED2E820S
designator C?, comment ValueDisplayed: 82µF  (hidden comment: UCY2W820MHD6)
CAP ALUM 82UF 20% 450V RADIAL; Polarized: Y; CompType: Capacitor; U/M: EA; Cap_F: 0.000082; Tolerance_%: 20; VDC_V: 450; IRMS_A: 730mA; TaMin_C: -25; TaMax_C: 105; AC_Derating: 0.3
signal-integrity model Cap
simulation model Cap
footprint CAPPR750W80D1600H4000 (Footprint not found)
footprint CAPPRD750W80D1800H3150 (CAPACITOR, POLARIZED, 0.8MM LEAD DIA, PITCH 7.5MM)
pins: 1 +, 2 -

## FCC_disclaimer
designator Logo?, comment FCC disclaimer  (no BOM)
FCC_disclaimer; SymbolCreator: codlsc
footprint FCC_disclaimer
footprint FCC_disclaimer_stacked

## Fiducial
designator FID?  (value not drawn)
Fiducial mark.  There is nothing to buy or mount.; SymbolCreator: codlsc
footprint Fiducial10-30
footprint Fiducial10-20
footprint Fiducial15-30
footprint Fiducial20-40
footprint Fiducial6.4-20

## GBU4A-BP
designator BR?, comment GBU6J
RECT BRIDGE GPP 6A 600V GBU; Manufacturer: Micro Commercial Components; CompType: Diode; U/M: EA; Vf_V: 0.95; Io_A: 4; Vr_V: 50; Value2: 50V; TJmax_C: 150; RJC_CperW: 2.2
footprint GBU (Comchip / Diodes Inc diode bridge)
pins: 1 +, 2 ~, 3 ~, 4 -

## GRM21BR71H474KA88L
designator C?  ValueDisplayed: 0.47µF  (hidden comment: GRM21BR71H474KA88L)
CAP, CERM, 0.47 µF, 50 V, +/- 10%, X7R, 0805; Manufacturer: MuRata; Polarized: N; CompType: Capacitor; Value: 0.47uF; U/M: EA; Cap_F: 0.00000047; Tolerance_%: 10; Value1: Unknown; VDC_V: 50; Value2: 50V; TaMin_C: -55; TaMax_C: 125; Cap_Case: 0805
signal-integrity model Cap
simulation model Cap
footprint 0805_HV
footprint 0805
footprint 0805M
footprint 0805L
pins: 1, 2

## GRM188R61C104KA01D
designator C?  ValueDisplayed: 0.1µF  (hidden comment: GRM188R61C104KA01D)
CAP, CERM, 0.1 µF, 16 V, +/- 10%, X5R, 0603; Manufacturer: MuRata; Polarized: N; CompType: Capacitor; Value: 0.1uF; U/M: EA; Cap_F: 0.0000001; Tolerance_%: 10; Value1: Unknown; VDC_V: 16; Value2: 16V; TaMin_C: -55; TaMax_C: 85; Cap_Case: 0603
signal-integrity model Cap
simulation model Cap
footprint 0603
footprint 0603M
footprint 0603L
footprint 0603_HV
footprint 0603S
pins: 1, 2

## GRM188R61H105KAALD
designator C?  ValueDisplayed: 1µF  (hidden comment: GRM188R61H105KAALD)
CAP, CERM, 1 µF, 50 V, +/- 10%, X5R, 0603; Manufacturer: MuRata; Polarized: N; CompType: Capacitor; Value: 1uF; U/M: EA; Cap_F: 0.000001; Tolerance_%: 10; Value1: Unknown; VDC_V: 50; Value2: 50V; TaMin_C: -55; TaMax_C: 85; Cap_Case: 0603
signal-integrity model Cap
simulation model Cap
footprint 0603
footprint 0603M
footprint 0603L
footprint 0603_HV
footprint 0603S
pins: 1, 2

## HLMP1523
designator D?, comment value Green  (hidden comment: HLMP1503)
LED SS HI EFF GREEN DIFF 3MM; Manufacturer: Everlight; Vf_V: 2.2; Value2: 2.2V; Io_A: 0.02; Tjmax_C: 100; Value1: W; U/M: EA
signal-integrity model Diode
footprint LED_HLMP1523 (Everlight Electronics)
pins: 1 A, 2 K

## IPP50R199CP
designator Q?, comment AOTF11S65L
MOSFET N-CH 650V 11A TO220F; Manufacturer: Alpha & Omega Semiconductor Inc.; Alternate Manufacturer: None; U/M: EA; ChType: N; VdsMax_V: 650; Value1: 399 mohm; Rdson45_ohm: 0; Value2: 13.2nC; QgTyp_nC: 34; Vgs_V: 20
footprint TO-220AB
footprint TO-220AB_HORIZONTAL
footprint TO-220AB_HORIZONTAL_SMT
footprint TO-220AB_100mil
footprint TO-220AB_Horizontal_100mil
footprint TO-220_FullPAK_Offset (Infineon  PG-TO220-3-31)
pins: 1 G, 2 D, 3 S
1 alternate drawing of the same symbol

## IRFB4410ZPBF
designator Q?, comment IRFI4227PBF
MOSFET N-CH 200V 26A TO-220FP; Manufacturer: International Rectifier; Alternate Manufacturer: None; U/M: EA; ChType: N; VdsMax_V: 200; Value1: 25 mOhm @ 17A, 10V; Value2: 100 nC; QgTyp_nC: 100nC at 10V; Vgs_V: 20; IdsMax_A: 97
footprint TO-220AB (Copied from Altium's version of TO3B)
footprint TO-220AB_HORIZONTAL
footprint TO-220AB_HORIZONTAL_SMT
footprint TO-220AB_100mil
pins: 1 G, 2 D, 3 S
1 alternate drawing of the same symbol

## LM5050-2
designator U?
High Side OR-ING FET Controller; Manufacturer: Texas Instruments; SymbolVersion: use current date i.e. 2008-05-20; SymbolCreator: Use LDAP id; CompType: Used in some BOM reports.  Useful for finding later.; U/M: EA, IN, or GM
footprint tsop-6 (TSOP, 6-Leads, Body 3.1x1.7mm (max), Pitch 0.95mm, IPC Medium Density)
pins: 1 nFGD, 2 GND, 3 OFF, 4 IN, 5 GATE, 6 OUT

## LTV-817
designator U?
Optocoupler, 5 kV, 50-600% CTR, TH-4; Manufacturer: Lite-On; U/M: EA; CTR_Min: 50% @ 5mA; CTR_Max: 600% @ 5mA; Voltage_Isolation_Vrms: 5000; tr_typ: 4us; tf_typ: 3us
footprint DIP762W60P254L460H350Q4B
pins: 1 A, 2 K, 3 E, 4 C

## MMBT2907A, Fairchild Semiconductor
designator Q?, comment MMBT4403WT1G  (value not drawn)
Transistor, PNP, 40 V, 0.6 A, SOT-323; Manufacturer: ON Semiconductor; CompType: BJT; PNP: 1; NPN: 0; Vceo_V: 40; Vcesat1_V: 0.75; Value: 40 V; IcRated_A: 0.8; Value1: 0.6 A; HfeMax: 300; TaMin_C: -55; TaMax_C: 150; U/M: EA
footprint SOT-323 (Zetex recommended land pattern.  March 2007)
footprint SOT-23M
footprint SOT-23L
pins: 1 B, 2 E, 3 C

## MMSZ5252B-7-F
designator D?  value 24V  (hidden comment: MMSZ5252B-7-F)
Diode, Zener, 24V, 500mW, SOD-123; Manufacturer: Diodes Inc.; SymbolCreator: a0412235; U/M: EA; Power_W: 0.5; Vz_V: 24; Value1: 0.5W; RJA_CperW: 350
signal-integrity model Diode
footprint SOD-123
pins: 1 K, 2 A

## Pb-Free
designator Logo?, comment Pb-Free Symbol  (no BOM)
SymbolCreator: a0412235
footprint Pb-Free_Overlay_Medium
footprint Pb-Free_Overlay_Small

## PCB
designator !PCB?, comment Printed Circuit Board  (value not drawn)  (mechanical)
Manufacturer: Any; SymbolCreator: a0412235; CompType: PCB
1 alternate drawing of the same symbol

## PCC-SMP-CLIP
designator M?, comment 4880G
MOUNTING KIT TO-220; Manufacturer: Aavid Thermalloy; SymbolCreator: Altium; CompType: Hardware

## PMSSS 440 0025 PH
designator H?
MACHINE SCREW PAN PHILLIPS 4-40; Manufacturer: B&F Fastener Supply; SymbolCreator: a0412235; CompType: Standoff
footprint B_F_PMSSS4400025PH

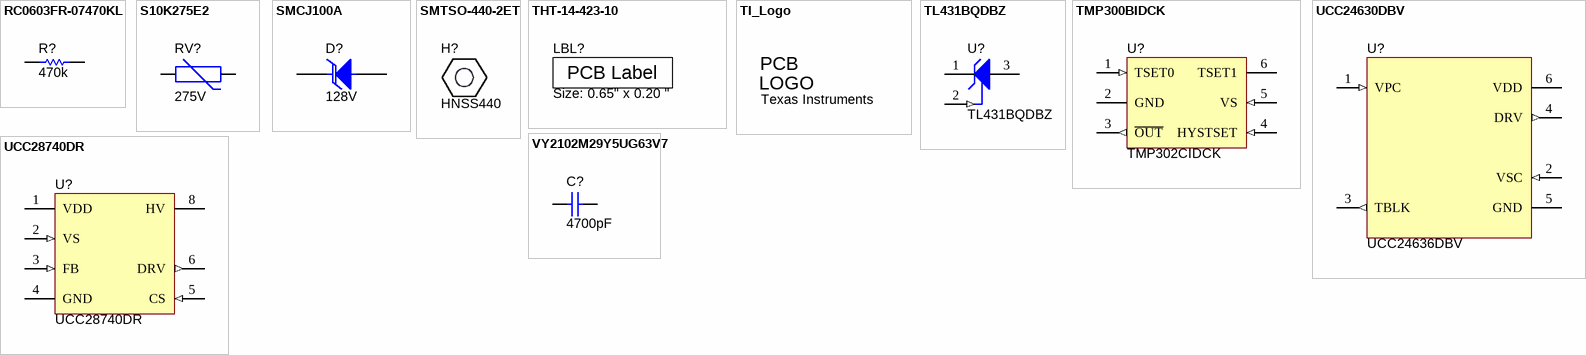
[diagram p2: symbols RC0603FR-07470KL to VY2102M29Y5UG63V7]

## RC0603FR-07470KL
designator R?  ValueDisplayed: 470k  (hidden comment: RC0603FR-07470KL)
RES, 470 k, 1%, 0.1 W, 0603; Manufacturer: Yageo America; CompType: Resistor; Value: 470k; Res_ohm: 470000; Tolerance_%: 1; Power_W: 0.1; Value2: 0.1W; VDC_V: 150; TempCo: 200 ppm/C; U/M: EA
signal-integrity model Resistor
simulation model Resistor
footprint 0603
footprint 0603M
footprint 0603L
footprint 0603_HV
footprint 0603S
pins: 1, 2

## S10K275E2
designator RV?  value 275V  (hidden comment: S10K275E2)
Varistor 275V RMS 10MM Radial, TH; Manufacturer: EPCOS Inc; SymbolCreator: a0412235
footprint VAR_S10K275E2 (EPCOS)
pins: 1, 2

## SMCJ100A
designator D?, comment value 128V  (hidden comment: 1.5KE150A)
TVS DIODE 128VWM 207VC AXIAL; Manufacturer: Littelfuse; U/M: EA; Power_W: 1500; Vr_V: 100; Value1: 1500W; RJA_CperW: 75
footprint SMC
footprint DO-201AD_Vert (DO-201AD VERTICAL FOOTPRINT)
pins: 1 K, 2 A

## SMTSO-440-2ET
designator H?, comment HNSS440
HEX NUT 1/4" STN STEEL 4-40; Manufacturer: B&F Fastener Supply; SymbolCreator: a0412235; CompType: Hardware

## THT-14-423-10
designator LBL?, comment Size: 0.65" x 0.20 "
Thermal Transfer Printable Labels, 0.650" W x 0.200" H - 10,000 per roll; Manufacturer: Brady; PartNumber: THT-14-423-10; SymbolCreator: a0412235; CompType: Label
footprint Label_650x200

## TI_Logo
designator Logo?, comment Texas Instruments  (no BOM)
Texas Instrument Corporate Signature; SymbolCreator: a0412235
footprint TI_Stacked_SolderMask_Medium
footprint TI_Stacked_SolderMask_Medium_Vertical
footprint TI_STACKED_OVERLAY_SMALL
footprint TI_Stacked_SolderMask_Small_Vertical
footprint TI_Stacked_Overlay_Medium
footprint TI_Stacked_Overlay_Medium_Vertical
footprint TI_Stacked_Overlay_Small
footprint TI_Stacked_Overlay_Small_Vertical
footprint TI_Horizontal_SolderMask_Small
footprint TI_Horizontal_Overlay_Medium
footprint TI_Horizontal_Overlay_Small
footprint TI_Symbol_SolderMask_Medium
footprint TI_Symbol_SolderMask_Small
footprint TI_Symbol_Overlay_Medium
footprint TI_Symbol_Overlay_Small
footprint TI_Horizontal_SolderMask_Medium

## TL431BQDBZ
designator U?
Precision VREF Shunt Adjustable; Alternate Manufacturer: Texas Instruments; SymbolCreator: a0412235; CompType: IC; U/M: EA
footprint DBZ0003A_N
footprint DBZ0003A_M
footprint DBZ0003A_L
pins: 1 CATHODE, 2 REF (in), 3 ANODE

## TMP300BIDCK
designator U?, comment TMP302CIDCK
Low-Power,  Low-Supply  Temperature  Switch; Alternate Manufacturer: None; Manufacturer: Texas Instruments; SymbolCreator: a0412235; CompType: IC; U/M: EA
footprint DCK0006A_N (SOT23, 6-Leads, Body 2x1.3mm, Pitch 0.65mm, Lead Span 2.1mm, IPC Medium Density)
footprint DCK0006A_M
footprint DCK0006A_L
pins: 1 TSET0 (in), 2 GND (power), 3 ~{OUT} (out), 4 HYSTSET (in), 5 VS (in), 6 TSET1 (power)

## UCC24630DBV
designator U?, comment UCC24636DBV
Sync. Rectifier Controller; Manufacturer: Texas Instruments; SymbolCreator: a0411947; CompType: IC; U/M: EA
footprint DBV0006A_N
footprint DBV0006A_M
footprint DBV0006A_L
pins: 1 VPC (in), 2 VSC (in), 3 TBLK (out), 4 DRV (out), 5 GND (power), 6 VDD (power)

## UCC28740DR
designator U?
Constant-Voltage, Constant-Current Flyback Controller Using Opto-Coupler Feedback, D0007A; Manufacturer: Texas Instruments; SymbolCreator: a0412235; CompType: IC; U/M: EA
footprint D0007A_N
footprint D0007A_M
footprint D0007A_L
pins: 1 VDD (power), 2 VS (in), 3 FB (in), 4 GND (power), 5 CS (in), 6 DRV (out), 8 HV (power)

## VY2102M29Y5UG63V7
designator C?, comment ValueDisplayed: 4700pF  (hidden comment: VY2472M49Y5US63V7)
CAP CER 4700PF 440VAC Y5U RADIAL; Manufacturer: Vishay-Bccomponents; Polarized: N; CompType: Capacitor; U/M: EA; Tolerance_%: 20; Value1: Unknown; Value2: 300; TaMin_C: -40; TaMax_C: 125; Cap_Case: Radial Disc 7.5mm, ls=7.5; AEC Category: Q200
signal-integrity model Cap
simulation model Cap
footprint CAPRD750W60D750H1050 (Vishay BC Components)
pins: 1, 2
